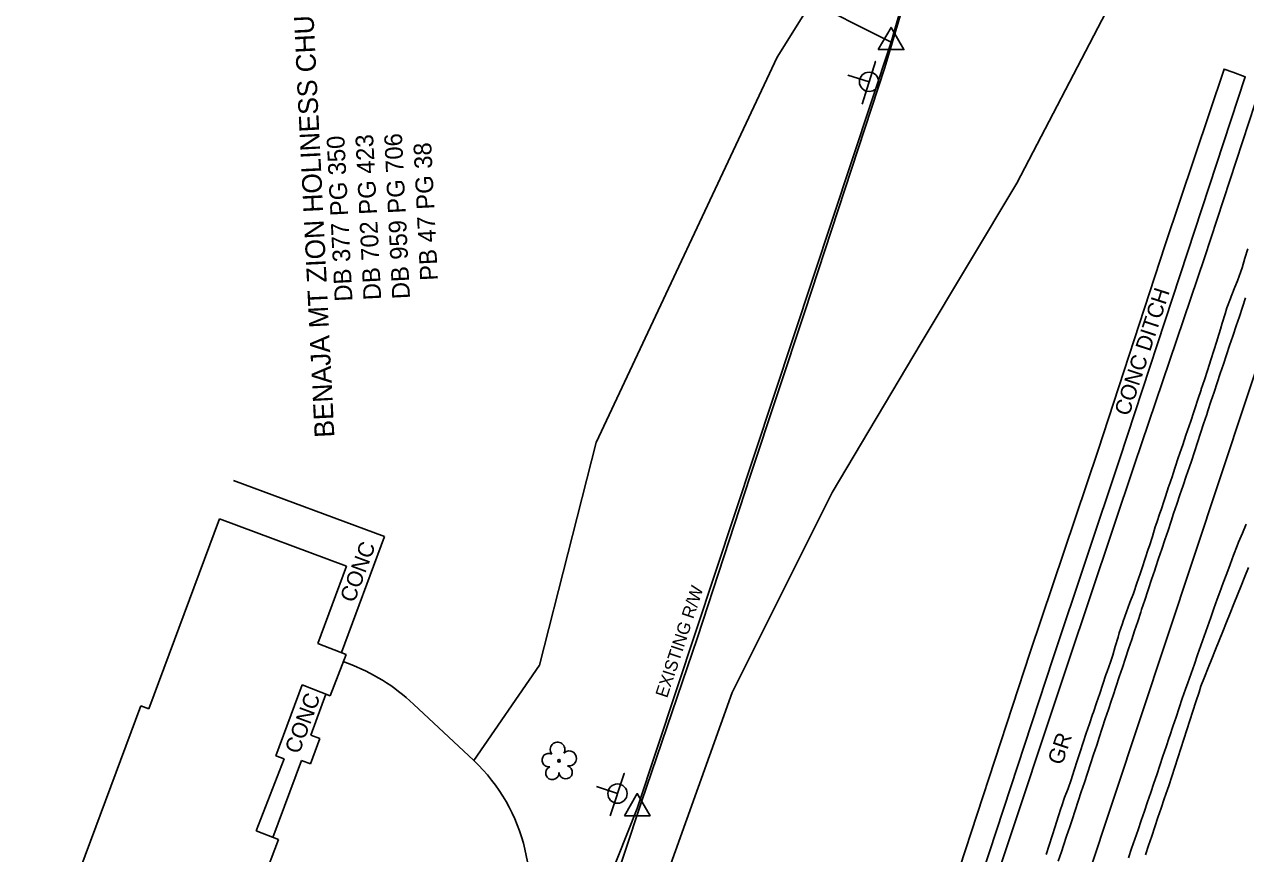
# Model space of a CAD drawing. Extents: x 1806071 to 1809844, y 912722 to 917035.
# Drawn here: x 1807370.6 to 1807680.7, y 914752.9 to 914963.4 of the extents above; entities that cross this region are included whole.
import ezdxf

# ---------------------------------------------------------------- set-up
doc = ezdxf.new("R2010")
doc.units = 0
for name, color, linetype in [('Exist Building', 7, 'Continuous'), ('Exist Horizontal Alignment', 7, 'Continuous'), ('Exist Other Culture Area Outline Text', 7, 'Continuous'), ('Exist Other Culture Fence Line', 7, 'Continuous'), ('Exist Property Deed Book Text', 7, 'Continuous'), ('Exist Property Line', 7, 'Continuous'), ('Exist Property Owner Text', 7, 'Continuous'), ('Exist Right of Way Line', 7, 'Continuous'), ('Exist Right of Way Line Text', 7, 'Continuous'), ('Exist Right of Way Monument CELL', 7, 'Continuous'), ('Exist Roads EOP', 7, 'Continuous'), ('Exist Roads EOP Other', 7, 'Continuous'), ('Exist Roads EOT', 7, 'Continuous'), ('Exist Roads Soil', 7, 'Continuous'), ('Exist Roads Soil Text', 7, 'Continuous'), ('Exist Structure Minor Paved Ditch or Gutter', 7, 'Continuous'), ('Exist Structure Minor Paved Ditch or Gutter Text', 7, 'Continuous'), ('Exist Utilities Power Joint Use Telephone CELL', 7, 'Continuous'), ('Exist Utilities Water UG Line SUE LOS B', 7, 'Continuous'), ('Exist Vegetation Tree CELL', 7, 'Continuous')]:
    doc.layers.add(name, color=color, linetype=linetype)

msp = doc.modelspace()

# ---------------------------------------------------------------- linework, layer by layer
at = {"layer": 'Exist Building'}
for p, q in [((1807420.09, 914837.86), (1807402.15, 914789.62)), ((1807452.37, 914825.86), (1807420.09, 914837.86)), ((1807445.06, 914806.19), (1807452.37, 914825.86)), ((1807452.26, 914803.43), (1807445.06, 914806.19)), ((1807448.24, 914792.95), (1807452.26, 914803.43)), ((1807434.46, 914777.7), (1807441.14, 914795.67)), ((1807441.14, 914795.67), (1807448.24, 914792.95)), ((1807400.11, 914790.38), (1807369.49, 914708.03)), ((1807402.15, 914789.62), (1807400.11, 914790.38)), ((1807436.5, 914776.94), (1807434.46, 914777.7)), ((1807429.46, 914758.59), (1807436.5, 914776.94)), ((1807435.1, 914756.42), (1807429.46, 914758.59)), ((1807431.08, 914745.94), (1807435.1, 914756.42))]:
    msp.add_line(p, q, dxfattribs=at)
at = {"layer": 'Exist Horizontal Alignment'}
msp.add_line((1807640.41, 914746.29), (1807709.77, 914955.49), dxfattribs=at)
at = {"layer": 'Exist Other Culture Fence Line'}
msp.add_lwpolyline([(1807420.06, 914449.08), (1807437.56, 914499.34), (1807454.43, 914548.48), (1807469.99, 914594.83), (1807485.68, 914641.45), (1807500.22, 914684.48), (1807514.26, 914726.68), (1807527.29, 914765.96), (1807541.47, 914807.7), (1807554.84, 914848.72), (1807568.79, 914890.48), (1807589.07, 914952.46), (1807599.72, 914988.41), (1807613.51, 915037.41), (1807624.28, 915075.41), (1807640.3, 915130.15), (1807650.98, 915169.04)], dxfattribs=at)
at = {"layer": 'Exist Property Line'}
msp.add_line((1807398.79, 915055.5), (1807590.67, 914958.88), dxfattribs=at)
at = {"layer": 'Exist Right of Way Line'}
for p, q in [((1807590.67, 914958.88), (1807650.64, 915168.27)), ((1807590.67, 914958.88), (1807526.22, 914764.33)), ((1807526.22, 914764.33), (1807425.5, 914511.68))]:
    msp.add_line(p, q, dxfattribs=at)
at = {"layer": 'Exist Right of Way Monument CELL'}
for p, q in [((1807590.67, 914958.88), (1807590.67, 914958.88)), ((1807526.22, 914764.33), (1807526.22, 914764.33))]:
    msp.add_line(p, q, dxfattribs=at)
for points in [[(1807587.42, 914956.99), (1807590.67, 914962.63), (1807593.92, 914956.99)], [(1807522.97, 914762.45), (1807526.22, 914768.08), (1807529.47, 914762.44)]]:
    msp.add_lwpolyline(points, close=True, dxfattribs=at)
at = {"layer": 'Exist Roads EOP'}
for points in [[(1807630.07, 914752.62), (1807630.82, 914755.01), (1807631.58, 914757.39), (1807632.33, 914759.77), (1807633.09, 914762.16), (1807633.84, 914764.54), (1807633.9, 914764.7), (1807634.74, 914767.06), (1807635.59, 914769.41), (1807636.38, 914771.62), (1807637.15, 914774), (1807637.91, 914776.38), (1807638.65, 914778.66), (1807639.45, 914781.03), (1807640.24, 914783.4), (1807641.04, 914785.77), (1807641.84, 914788.14), (1807642.05, 914788.75), (1807642.84, 914791.12), (1807643.64, 914793.49), (1807644.43, 914795.86), (1807645.23, 914798.23), (1807645.53, 914799.12), (1807646.34, 914801.49), (1807646.95, 914803.25), (1807647.59, 914805.4), (1807648.29, 914807.8), (1807648.61, 914808.88), (1807649.4, 914811.26), (1807649.61, 914811.88), (1807650.47, 914814.22), (1807651.33, 914816.57), (1807652.19, 914818.92), (1807652.28, 914819.18), (1807653.08, 914821.54), (1807653.88, 914823.91), (1807654.39, 914825.44), (1807655.19, 914827.81), (1807655.98, 914830.18), (1807656.26, 914831.01), (1807657.01, 914833.4), (1807657.76, 914835.78), (1807658.11, 914836.91), (1807658.93, 914839.27), (1807659.21, 914840.1), (1807660, 914842.47), (1807660.36, 914843.55), (1807661.11, 914845.94), (1807661.19, 914846.18), (1807662, 914848.55), (1807662.28, 914849.36), (1807662.79, 914850.99), (1807663.6, 914853.36), (1807664.41, 914855.72), (1807664.73, 914856.68), (1807665.53, 914859.05), (1807665.95, 914860.3), (1807666.74, 914862.66), (1807667.54, 914865.03), (1807667.81, 914865.82), (1807668.59, 914868.19), (1807669.38, 914870.57), (1807669.44, 914870.76), (1807670.24, 914873.13), (1807671.03, 914875.5), (1807671.13, 914875.8), (1807671.88, 914878.18), (1807672.64, 914880.56), (1807673.39, 914882.95), (1807673.59, 914883.59), (1807674.32, 914885.98), (1807674.78, 914887.51), (1807675.49, 914889.9), (1807675.95, 914891.42), (1807676.82, 914893.76), (1807677.03, 914894.31), (1807677.97, 914896.63), (1807678.64, 914898.29), (1807679.45, 914900.66), (1807679.78, 914901.62), (1807680.5, 914904.02), (1807681.22, 914906.41)], [(1807655.23, 914752.56), (1807656.03, 914754.92), (1807656.84, 914757.29), (1807657.64, 914759.66), (1807658.44, 914762.03), (1807659.25, 914764.39), (1807660.05, 914766.76), (1807660.85, 914769.13), (1807661.16, 914770.02), (1807661.93, 914772.4), (1807662.7, 914774.77), (1807663.47, 914777.15), (1807664.24, 914779.53), (1807665.01, 914781.91), (1807665.78, 914784.29), (1807666.55, 914786.67), (1807667.32, 914789.04), (1807668.09, 914791.42), (1807668.86, 914793.8), (1807669.36, 914795.35), (1807670.29, 914797.67), (1807671.22, 914799.99), (1807672.15, 914802.31), (1807673.08, 914804.63), (1807674.01, 914806.95), (1807674.94, 914809.27), (1807675.87, 914811.59), (1807676.8, 914813.91), (1807677.73, 914816.23), (1807678.66, 914818.55), (1807679.59, 914820.87), (1807680.52, 914823.19), (1807681.45, 914825.51)]]:
    msp.add_lwpolyline(points, dxfattribs=at)
at = {"layer": 'Exist Roads EOP Other'}
for p, q in [((1807423.71, 914847.59), (1807462.01, 914833.36)), ((1807462.01, 914833.36), (1807451.07, 914803.89)), ((1807452.59, 914801.23), (1807451.56, 914801.61)), ((1807447.16, 914793.37), (1807443.29, 914782.95)), ((1807484.67, 914776.47), (1807469.4, 914790.81)), ((1807445.6, 914782.09), (1807443.21, 914775.66)), ((1807445.6, 914782.09), (1807443.29, 914782.95)), ((1807440.9, 914776.52), (1807433.64, 914756.98)), ((1807443.21, 914775.66), (1807440.9, 914776.52))]:
    msp.add_line(p, q, dxfattribs=at)
for centre, radius, start, end in [((1807435.18, 914754.35), 50, 46.814, 69.6237), ((1807453.88, 914743.66), 45, 339.6237, 46.814)]:
    msp.add_arc(centre, radius, start, end, dxfattribs=at)
at = {"layer": 'Exist Roads EOT'}
for points in [[(1807633.13, 914750.93), (1807633.92, 914753.3), (1807634.44, 914754.89), (1807635.23, 914757.26), (1807636.02, 914759.63), (1807636.61, 914761.41), (1807637.4, 914763.79), (1807638.18, 914766.16), (1807638.96, 914768.54), (1807639.74, 914770.91), (1807640.53, 914773.29), (1807641.31, 914775.66), (1807642.09, 914778.03), (1807642.87, 914780.41), (1807643.5, 914782.3), (1807644.28, 914784.68), (1807645.06, 914787.05), (1807645.85, 914789.42), (1807646.63, 914791.8), (1807647.02, 914792.98), (1807647.81, 914795.35), (1807648.6, 914797.72), (1807649.39, 914800.09), (1807650.18, 914802.46), (1807650.97, 914804.84), (1807651.76, 914807.21), (1807652.49, 914809.41), (1807653.28, 914811.79), (1807654.07, 914814.16), (1807654.29, 914814.83), (1807655.08, 914817.2), (1807655.88, 914819.57), (1807656.05, 914820.08), (1807656.83, 914822.45), (1807657.62, 914824.82), (1807657.82, 914825.41), (1807658.61, 914827.78), (1807659.4, 914830.15), (1807660.19, 914832.52), (1807660.99, 914834.89), (1807661.78, 914837.26), (1807662.42, 914839.18), (1807663.22, 914841.55), (1807664.02, 914843.92), (1807664.82, 914846.28), (1807665.62, 914848.65), (1807666.42, 914851.02), (1807666.91, 914852.47), (1807667.69, 914854.85), (1807668.47, 914857.22), (1807669.25, 914859.6), (1807670.03, 914861.97), (1807670.81, 914864.35), (1807671.1, 914865.24), (1807671.89, 914867.62), (1807672.68, 914869.99), (1807673.47, 914872.36), (1807674.26, 914874.73), (1807675.05, 914877.1), (1807675.84, 914879.48), (1807676.63, 914881.85), (1807677.42, 914884.22), (1807677.52, 914884.52), (1807678.32, 914886.89), (1807679.11, 914889.26), (1807679.9, 914891.63), (1807680.69, 914894)], [(1807680.85, 914836.51), (1807679.89, 914834.21), (1807678.92, 914831.9), (1807678.53, 914830.96), (1807677.65, 914828.62), (1807676.78, 914826.28), (1807675.9, 914823.93), (1807675.02, 914821.59), (1807674.14, 914819.25), (1807673.48, 914817.48), (1807672.65, 914815.12), (1807671.82, 914812.76), (1807670.99, 914810.4), (1807670.16, 914808.04), (1807669.33, 914805.69), (1807668.5, 914803.33), (1807667.67, 914800.97), (1807666.83, 914798.61), (1807666, 914796.25), (1807665.41, 914794.57), (1807664.61, 914792.2), (1807663.81, 914789.83), (1807663.02, 914787.46), (1807662.22, 914785.09), (1807661.42, 914782.73), (1807661.29, 914782.34), (1807660.5, 914779.97), (1807659.7, 914777.6), (1807658.91, 914775.22), (1807658.12, 914772.85), (1807657.4, 914770.7), (1807656.59, 914768.33), (1807655.79, 914765.97), (1807654.98, 914763.6), (1807654.17, 914761.23), (1807653.37, 914758.87), (1807652.56, 914756.5), (1807651.75, 914754.14), (1807650.95, 914751.77)]]:
    msp.add_lwpolyline(points, dxfattribs=at)
at = {"layer": 'Exist Roads Soil'}
for points in [[(1807561.73, 914955.04), (1807574.98, 914976.42), (1807592.82, 914999.8), (1807599.95, 915014.93), (1807600.53, 915017.47), (1807616.54, 915063.17), (1807630.22, 915114.17), (1807641.7, 915156.98), (1807650.35, 915195.77), (1807657, 915238.57), (1807661.75, 915283.27), (1807665.52, 915315.77), (1807671.94, 915359.18), (1807674.34, 915376.66), (1807677.79, 915390.04), (1807683.47, 915408.15), (1807694.91, 915435.78), (1807711.71, 915466.31), (1807727.99, 915486.87)], [(1807561.73, 914955.04), (1807515.81, 914857.23), (1807501.34, 914800.67), (1807484.67, 914776.47)], [(1807587.32, 914650.3), (1807600.85, 914696.35), (1807617.33, 914746.41), (1807635.67, 914801.34), (1807652.53, 914851.87), (1807670.27, 914904.1), (1807684.71, 914948.33)]]:
    msp.add_lwpolyline(points, dxfattribs=at)
at = {"layer": 'Exist Structure Minor Paved Ditch or Gutter'}
for points in [[(1807677.42, 914951.28), (1807675.23, 914952.04), (1807660.25, 914907.44), (1807643.26, 914855.26), (1807625.95, 914803.97), (1807608.03, 914749.12), (1807590.66, 914699.49), (1807576.44, 914654.84), (1807557.74, 914606.76), (1807547.78, 914582.96)], [(1807553.13, 914580.48), (1807563, 914604.26), (1807581.24, 914652.99), (1807597.04, 914697.72), (1807613.76, 914747.64), (1807631.84, 914802.55), (1807648.71, 914853.16), (1807665.9, 914905.5), (1807680.6, 914950.04), (1807677.42, 914951.28)]]:
    msp.add_lwpolyline(points, dxfattribs=at)
at = {"layer": 'Exist Utilities Power Joint Use Telephone CELL'}
for p, q in [((1807585.08, 914948.81), (1807585.08, 914948.81)), ((1807521.19, 914768.09), (1807521.19, 914768.09))]:
    msp.add_line(p, q, dxfattribs=at)
for points in [[(1807583.34, 914943.13), (1807586.69, 914953.97), (1807585.09, 914948.81), (1807579.7, 914950.46)], [(1807519.34, 914762.45), (1807522.91, 914773.21), (1807521.21, 914768.08), (1807515.85, 914769.85)]]:
    msp.add_lwpolyline(points, dxfattribs=at)
for centre in [(1807585.07, 914948.81), (1807521.18, 914768.09)]:
    msp.add_circle(centre, 2.45, dxfattribs=at)
at = {"layer": 'Exist Utilities Water UG Line SUE LOS B'}
msp.add_lwpolyline([(1807444.63, 914517.75), (1807458.92, 914541.8), (1807471.36, 914566.9), (1807491.53, 914623.01), (1807511.26, 914680.96), (1807530.12, 914737.44), (1807550.3, 914793.76), (1807575.73, 914844.54), (1807598.3, 914882.51), (1807622.62, 914923.09), (1807645.16, 914966.45)], dxfattribs=at)
at = {"layer": 'Exist Vegetation Tree CELL'}
msp.add_line((1807506.34, 914776.42), (1807506.34, 914776.42), dxfattribs=at)
msp.add_circle((1807506.34, 914776.42), 0.326, dxfattribs=at)
for centre, radius, start, end in [((1807505.95, 914779.3), 1.86, 330.1651, 219.7134), ((1807503.73, 914776.58), 1.73, 62.6636, 279.3457), ((1807508.89, 914777.01), 1.9, 257.1011, 134.1999), ((1807504.63, 914773.3), 1.69, 111.5671, 6.231), ((1807508.01, 914773.52), 1.7, 181.2822, 74.56)]:
    msp.add_arc(centre, radius, start, end, dxfattribs=at)

# ---------------------------------------------------------------- texts
at = {"layer": 'Exist Other Culture Area Outline Text'}
for p in [(1807454.33, 914816.34), (1807440.32, 914777.92)]:
    msp.add_text('CONC', height=4, rotation=69.6237, dxfattribs=at).set_placement(p)
at = {"layer": 'Exist Property Deed Book Text'}
for s, p in [('DB 702 PG 423', (1807461.19, 914893.49)), ('DB 959 PG 706', (1807468.5, 914893.75)), ('DB 377 PG 350', (1807453.89, 914893.13)), ('PB 47 PG 38', (1807475.59, 914898.43))]:
    msp.add_text(s, height=4.5, rotation=92.8422, dxfattribs=at).set_placement(p)
at = {"layer": 'Exist Property Owner Text'}
msp.add_text('BENAJA MT ZION HOLINESS CHURCH', height=5, rotation=92.8422, dxfattribs=at).set_placement((1807449.3, 914858.58))
at = {"layer": 'Exist Right of Way Line Text'}
msp.add_text('EXISTING R/W', height=3.2, rotation=71.669, dxfattribs=at).set_placement((1807533.76, 914792.19))
at = {"layer": 'Exist Roads Soil Text'}
msp.add_text('GR', height=4, rotation=71.5378, dxfattribs=at).set_placement((1807634.1, 914775.11))
at = {"layer": 'Exist Structure Minor Paved Ditch or Gutter Text'}
msp.add_text('CONC DITCH', height=4, rotation=71.9031, dxfattribs=at).set_placement((1807651.07, 914863.74))

doc.saveas('drawing.dxf')
